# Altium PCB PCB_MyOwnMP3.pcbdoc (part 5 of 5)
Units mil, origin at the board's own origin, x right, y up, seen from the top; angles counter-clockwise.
Board outline 3605 x 4860 mil, 6 copper layers (Top Layer, Inner1, Inner2, Inner3, Inner4, Bottom Layer); 291 components, 261 nets, 1070 pads, 1658 vias.
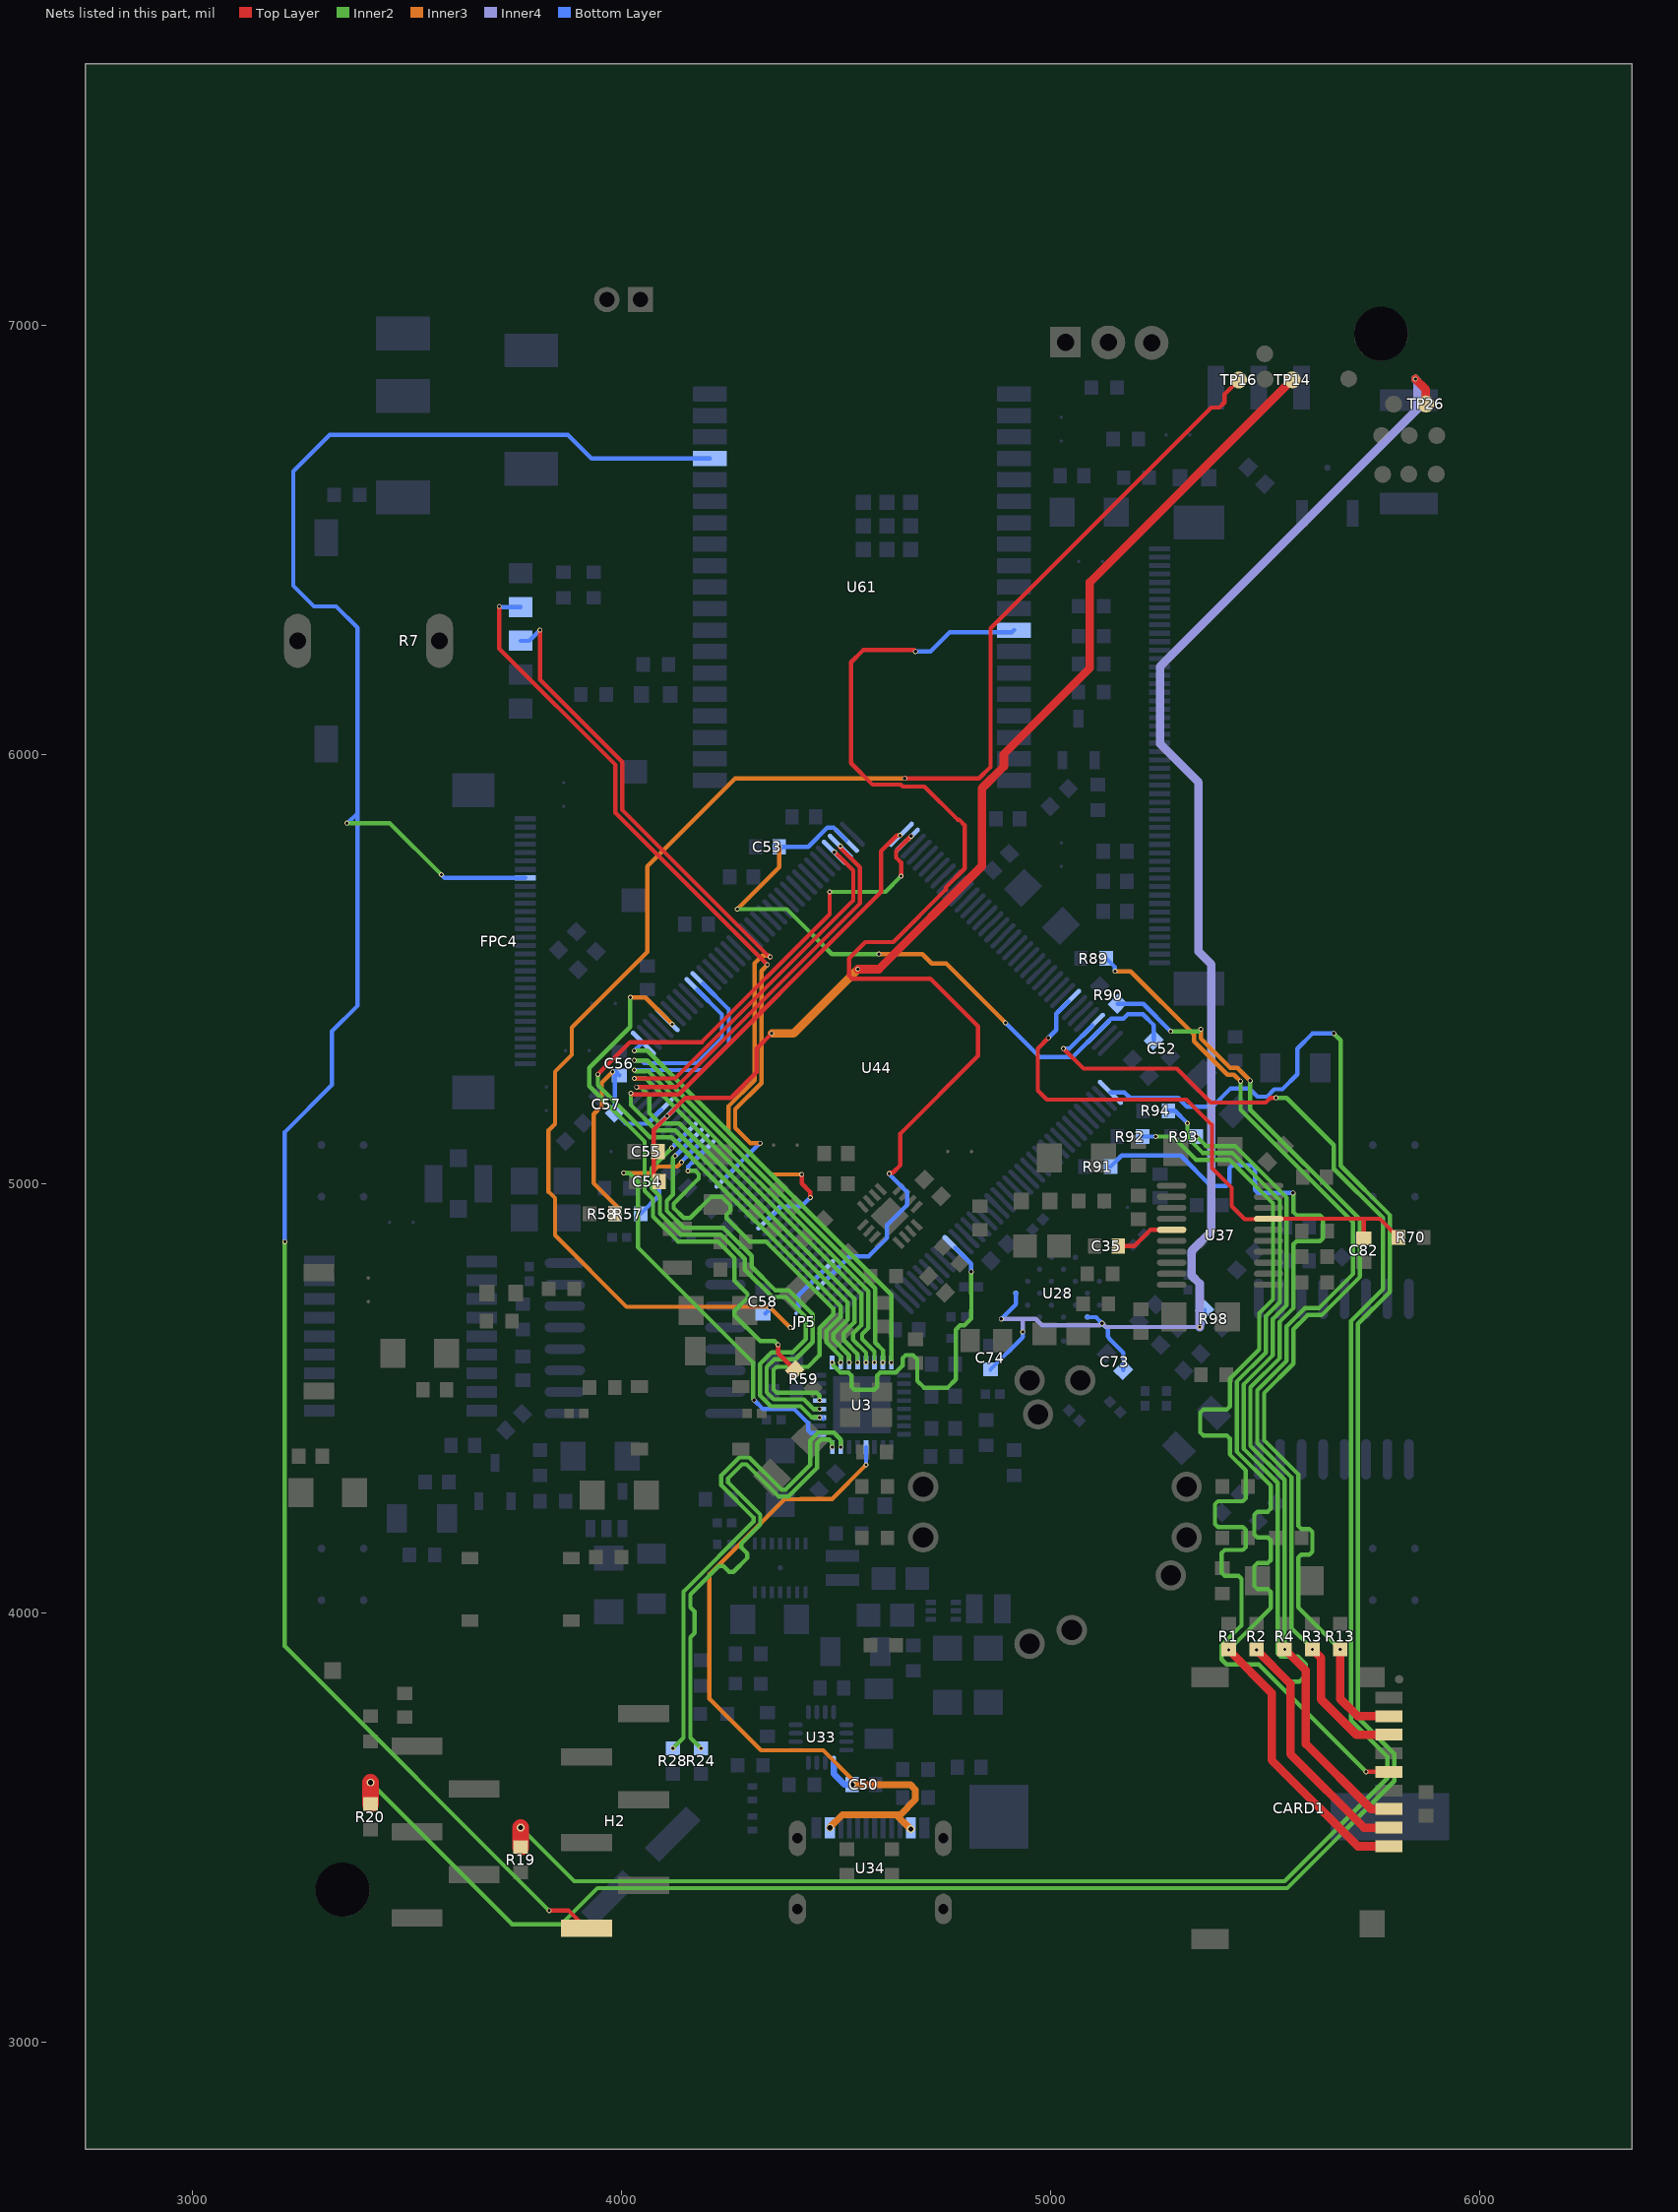
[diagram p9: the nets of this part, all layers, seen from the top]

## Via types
v1: diameter 11.42, hole 7.48, Top Layer to Bottom Layer, 1536 vias
v2: diameter 17.72, hole 11.81, Top Layer to Bottom Layer, 85 vias
v3: diameter 39.37, hole 29.53, Top Layer to Bottom Layer, 11 vias
v4: diameter 11.81, hole 7.87, Top Layer to Bottom Layer, 8 vias
v5: diameter 47.24, hole 23.62, Top Layer to Bottom Layer, 8 vias
v6: diameter 19.68, hole 11.81, Top Layer to Bottom Layer, 4 vias
v7: diameter 24.41, hole 12.2, Top Layer to Bottom Layer, 3 vias
v8: diameter 11.4, hole 7.5, Top Layer to Bottom Layer, 3 vias

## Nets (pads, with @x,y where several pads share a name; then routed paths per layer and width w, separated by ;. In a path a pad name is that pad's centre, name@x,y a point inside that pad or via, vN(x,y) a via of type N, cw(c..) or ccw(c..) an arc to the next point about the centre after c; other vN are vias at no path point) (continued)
SD_A: U44.5 U61.12 | length 2617.7
  Top Layer w10: v1(4623.55,5023.55) 4625.73,5025.73 4632.35,5025.73 4650,5043.38 4650,5117.02 4830.98,5298 4830.98,5366.63 4719.69,5477.93 4537.07,5477.93 4530,5485 4530,5524.79 4568.24,5563.03 4633.58,5563.03 4755.98,5685.44 4755.98,5690.44 4800,5734.45 4800,5835 4786.69,5848.31 4783.09,5848.31 4705.95,5925.45 4655.28,5925.45 4650.72,5930 4585,5930 4535,5980 4535,6215 4563.31,6243.31 4681.69,6243.31 v1(4685,6240)
  Bottom Layer w10: U44.5@4482.25,4781.42 4531.69,4830.86 4575.87,4830.86 4619.02,4874.01 4619.02,4904.02 4665.8,4950.8 4665.8,4980.29 4623.55,5022.54 v1(4623.55,5023.55) ; v1(4685,6240) 4720,6240 4765,6285 4909.33,6285 U61.12@4914.33,6290
SD_CLK: CARD1.5 R92.2 | length 2341
  Top Layer w10: v1(5735,3630) 5788.31,3630 CARD1.5@5788.66,3629.65
  Inner2 w10: v1(5245,5110) 5285,5110 5339.02,5055.98 5416.62,5055.98 5518.27,4954.33 5518.27,4730.67 5486.09,4698.49 5486.09,4613.91 5417.68,4545.5 5417.68,4480.86 5410.61,4473.79 5355.77,4473.79 5348.7,4466.72 5348.7,4420.86 5355.77,4413.79 5410.61,4413.79 5417.68,4406.72 5417.68,4369.5 5455,4332.18 5455,4267.3 5447.93,4260.23 5390.03,4260.23 5382.96,4253.16 5382.96,4207.3 5390.03,4200.23 5447.93,4200.23 5455,4193.16 5455,4153.76 5447.93,4146.69 5405.77,4146.69 5398.7,4139.62 5398.7,4093.76 5405.77,4086.69 5437.93,4086.69 5445,4079.62 5445,3971.11 5398.31,3924.41 5398.31,3891.69 5410,3880 5485,3880 v1(5735,3630)
  Bottom Layer w10: R92.2@5214.66,5110 v1(5245,5110)
SD_CMD: CARD1.3 R4.1 R91.2 | length 2318.2
  Top Layer w19.68: v1(5545.71,3915.34) 5595,3866.05 5595,3695 5746.97,3543.03 CARD1.3@5788.66,3543.03
  Inner2 w10: v1(5545.71,3915.34) 5545,3916.05 5545,4310 5465.64,4389.36 5465.64,4525.64 5534.05,4594.05 5534.05,4678.62 5566.23,4710.81 5566.23,4859.24 5573.3,4866.31 5627.93,4866.31 5635,4873.38 5635,4919.24 5627.93,4926.31 5573.3,4926.31 5566.23,4933.38 5566.23,4975 5565,4976.23 v1(5565,4978.47)
  Bottom Layer w10: R91.2@5139.66,5040 5165.68,5066.02 5303.05,5066.02 5374.07,4995 5409.39,4995 5416.46,5002.07 5416.46,5035.89 5423.53,5042.96 5469.39,5042.96 5476.46,5035.89 5476.46,4985.54 5483.53,4978.47 v1(5565,4978.47)
SD_DATA0: CARD1.7 R3.1 R89.2 | length 2360.8
  Top Layer w19.68: v1(5610,3915.34) 5630,3895.34 5630,3798.7 5712.44,3716.26 CARD1.7@5788.66,3716.26
  Inner2 w10: v1(5442.5,5238.89) 5442.5,5172.5 5705,4910 5705,4790 5625,4710 5592.39,4710 5550.03,4667.63 5550.03,4587.42 5481.62,4519.02 5481.62,4395.98 5560.98,4316.62 5560.98,3965 5610,3915.98 v1(5610,3915.34)
  Inner3 w10: v1(5150,5495) 5186.39,5495 5334.02,5347.38 5334.02,5331.99 5411.99,5254.02 5427.38,5254.02 v1(5442.5,5238.89)
  Bottom Layer w10: R89.2@5129.66,5525 5150,5504.66 v1(5150,5495)
SD_DATA1: CARD1.8 R13.1 R90.2 | length 2310.9
  Top Layer w19.68: v1(5675,3915.34) 5675,3800 5715.43,3759.57 CARD1.8@5788.66,3759.57
  Inner2 w10: v1(5280,5355) 5345,5355 v1(5350,5360) ; v1(5465,5240) 5465,5172.61 5720.98,4916.62 5720.98,4783.38 5631.62,4694.02 5599.02,4694.02 5566.01,4661.01 5566.01,4580.8 5497.61,4512.39 5497.61,4402.61 5576.97,4323.24 5576.97,4202.9 5584.04,4195.83 5602.93,4195.83 5610,4188.76 5610,4142.9 5602.93,4135.83 5584.04,4135.83 5576.97,4128.76 5576.97,4013.37 v1(5675,3915.34)
  Inner3 w10: v1(5350,5360) 5350,5338.61 5418.61,5270 5435,5270 v1(5465,5240)
  Bottom Layer w10: R90.2@5155.97,5419.03 5215.97,5419.03 v1(5280,5355)
SD_DATA2: CARD1.1 R1.1 R94.2 | length 2302.5
  Top Layer w19.68: v1(5415,3913.7) 5515,3813.7 5515,3657.4 5715.98,3456.42 CARD1.1@5788.66,3456.42
  Inner2 w10: v1(5318.71,5140.89) 5318.71,5107.68 5354.42,5071.97 5423.24,5071.97 5534.26,4960.95 5534.26,4724.05 5502.08,4691.87 5502.08,4607.29 5433.67,4538.88 5433.67,4376.12 5513.03,4296.76 5513.03,4243.07 5505.96,4236 5481.87,4236 5474.8,4228.92 5474.8,4183.07 5481.87,4176 5505.96,4176 5513.03,4168.92 5513.03,4123.07 5505.96,4116 5481.87,4116 5474.8,4108.92 5474.8,4063.07 5481.87,4056 5505.96,4056 5513.03,4048.92 5513.03,4011.73 v1(5415,3913.7)
  Bottom Layer w10: R94.2@5274.66,5170 5289.6,5170 v1(5318.71,5140.89)
SD_DATA3: CARD1.2 R2.1 R93.2 | length 2234.9
  Top Layer w19.68: v1(5480,3913.7) 5558.66,3835.04 5558.66,3671.34 5730.27,3499.73 CARD1.2@5788.66,3499.73
  Inner2 w10: v1(5340,5110) 5362.05,5087.95 5429.86,5087.95 5550.24,4967.57 5550.24,4717.43 5518.06,4685.25 5518.06,4600.67 5449.65,4532.26 5449.65,4382.74 5529.02,4303.38 5529.02,3905.98 5536.35,3898.65 5576.35,3898.65 5595,3880 5595,3855 5580,3840 5553.7,3840 v1(5480,3913.7)
SWCLK: R20.1 U44.109 | length 5229.8
  Top Layer w39.37: R20.1@3415,3554.66 v2(3415,3605)
  Inner2 w10: v2(3415,3605) 3745,3275 3860,3275 3944.02,3359.02 5551.62,3359.02 5800.98,3608.38 5800.98,3671.62 5716.09,3756.52 5716.09,4673.48 5790.98,4748.38 5790.98,4926.62 5675.98,5041.62 5675.98,5334.02 v1(5660,5350)
  Bottom Layer w10: U44.109@5139.25,5212.93 5172.07,5212.93 5185.12,5199.88 5297.51,5199.88 5318.38,5179.02 5376.62,5179.02 5419.81,5222.2 5462.8,5222.2 5481.91,5203.09 5504.27,5203.09 5521.18,5220 5540,5220 5575,5255 5575,5315 5610,5350 v1(5660,5350)
SWDIO: R19.1 U44.105 | length 4627.6
  Top Layer w10: v1(5030,5315) 5076.69,5268.31 5294.09,5268.31 5373.38,5189.02 5501.15,5189.02 5512.34,5200.21 v1(5525,5200.21)
  Top Layer w39.37: R19.1@3765,3454.66 v2(3765,3500)
  Inner2 w10: v2(3765,3500) 3890,3375 5545,3375 5785,3615 5785,3665 5700.11,3749.89 5700.11,4680.11 5775,4755 5775,4920 5660,5035 5660,5090 5549.79,5200.21 v1(5525,5200.21)
  Bottom Layer w10: v1(5030,5315) 5043.66,5315 U44.105@5097.49,5368.83
TXD0: FPC4.23 H2.1 U61.35 | length 5407.7
  Top Layer w10: v1(3831.48,3306.48) 3876.98,3306.48 H2.1@3918.46,3265
  Inner2 w10: v1(3215.32,4865) 3215.32,3922.64 v1(3831.48,3306.48) ; v1(3360,5840) 3460,5840 v1(3580,5720)
  Bottom Layer w10: v1(3215.32,4865) 3215.32,5120.32 3325.32,5230.32 3325.32,5355.32 3385,5415 3385,5863.57 ; v1(3360,5840) 3361.43,5840 3385,5863.57 ; v1(3580,5720) 3587.36,5712.64 FPC4.23@3775.53,5712.64 ; U61.35@4205.67,6690 4205.09,6689.42 3930.58,6689.42 3875,6745 3320,6745 3235,6660 3235,6393.38 3283.38,6345 3335,6345 3385,6295 3385,5863.57
ULPI.CLK: R59.1 U44.41 | length 1329.2
  Top Layer w10: v1(4365,4625) 4365,4605 R59.1@4404.03,4565.97
  Inner2 w10: v1(4020.35,5434.26) 4020,5433.91 4020,5365 3925,5270 3925,5227.39 4054.02,5098.38 4054.02,4983.38 4073.47,4963.93 4073.47,4923.72 4131.6,4865.58 4224.42,4865.58 4263.4,4826.6 4263.4,4773.99 4293.68,4743.71 4293.68,4733.71 4263.4,4703.43 4263.4,4693.43 4323.31,4633.53 4356.47,4633.53 v1(4365,4625)
  Inner3 w10: v1(4020.35,5434.26) 4055.74,5434.26 4118.07,5371.93 v1(4118.07,5371.39)
ULPI.D0: U3.24 U44.37 | length 1020
  Inner2 w10: v1(4030,5310) 4060,5310 4628.84,4741.16 v1(4628.84,4583.42)
  Bottom Layer w10: v1(4030,5310) 4047.07,5327.07 U44.37@4050.75,5327.07
ULPI.D1: U3.23 U44.46 | length 1329.5
  Inner2 w10: v1(4030,5287.4) 4059.99,5287.4 4590.98,4756.41 4590.98,4630.33 4609.15,4612.17 v1(4609.15,4583.42)
  Bottom Layer w10: v1(4030,5287.4) 4046.21,5287.4 4052.67,5280.94 4175.94,5280.94 4234.02,5339.02 4234.02,5394.36 U44.46@4176.03,5452.35
ULPI.D2: U3.22 U44.47 | length 1354.2
  Inner2 w10: v1(4030.05,5264.95) 4032.99,5262.01 4056.91,5262.01 4057.62,5262.71 4062.08,5262.71 4575,4749.79 4575,4664 4560.59,4649.59 4560.59,4638.12 4589.47,4609.24 v1(4589.47,4583.42)
  Bottom Layer w10: v1(4030.05,5264.95) 4189.95,5264.95 4250,5325 4250,5406.2 U44.47@4189.94,5466.26
ULPI.D3: U3.21 U44.69 | length 1730.4
  Top Layer w10: v1(4030,5245.31) 4125.1,5245.31 4540,5660.21 4540,5730 4497.51,5772.49 v1(4496.17,5772.49)
  Inner2 w10: v1(4030,5245.31) 4056.87,5245.31 4558.68,4743.5 4558.68,4670.29 4539.2,4650.8 4539.2,4636.91 4569.78,4606.33 v1(4569.78,4583.42)
ULPI.D4: U3.20 U44.70 | length 1758
  Top Layer w10: v1(4035,5225) 4127.39,5225 4555.98,5653.59 4555.98,5736.62 4510.09,5782.51 v1(4510.09,5786.41)
  Inner2 w10: v1(4035,5225) 4045,5225 4065,5205 4065,5165 4089.64,5140.36 4134.64,5140.36 4542.7,4732.3 4542.7,4676.91 4517.9,4652.1 4517.9,4635.61 4550.1,4603.4 v1(4550.1,4583.42)
ULPI.D5: U3.19 U44.73 | length 1826
  Top Layer w10: v1(4021.69,5210.76) 4024.14,5208.31 4133.31,5208.31 4605,5680 4605,5775 4641.47,5811.47 v1(4649.28,5811.47)
  Inner2 w10: v1(4021.69,5210.76) 4021.69,5183.31 4080.62,5124.38 4125.62,5124.38 4526.71,4723.29 4526.71,4683.53 4493.51,4650.32 4493.51,4637.39 4530.41,4600.49 v1(4530.41,4583.42)
ULPI.D6: U3.18 U44.74 | length 2003.8
  Top Layer w10: v1(3945,5255) 4020,5330 4187.18,5330 4485,5627.82 v1(4485,5680) ; v1(4651.54,5716.46) 4651.54,5748.46 4640,5760 4640,5775 v1(4675,5810)
  Inner2 w10: v1(3945,5255) 3945,5230 4066.61,5108.39 4116.61,5108.39 4510.73,4714.27 4510.73,4690.15 4477.52,4656.94 4477.52,4630.77 4510.73,4597.56 v1(4510.73,4583.42) ; v1(4485,5680) 4615.08,5680 v1(4651.54,5716.46)
ULPI.D7: U3.17 U44.135 | length 802.8
  Inner2 w10: v1(4491.04,4583.42) 4494.04,4580.42 4494.04,4575.96 4510,4560 4528.73,4560 4535.8,4552.93 4535.8,4527.19 4542.87,4520.12 4588.73,4520.12 4595.8,4527.19 4595.8,4552.93 4602.87,4560 4639.03,4560 4655.53,4576.51 4655.53,4593.8 4662.6,4600.87 4679.13,4600.87 4689.13,4590.87 4689.13,4540.87 4705,4525 4760,4525 4779.02,4544.02 4779.02,4660.13 4789.02,4670.13 4799.24,4670.13 4814.97,4685.86 4814.97,4705.31 4815.22,4705.56 4815.22,4743.97 4814.97,4744.22 v1(4815,4795)
  Bottom Layer w10: U44.135@4777.35,4851.02 4815,4813.37 v1(4815,4795)
ULPI.DIR: U3.12 U44.28 | length 1037.3
  Inner2 w10: v8(4125,5065) 4120,5060 4120,4974.77 4105.43,4960.21 4105.43,4936.96 4144.85,4897.55 4237.66,4897.55 4303.35,4831.86 4303.35,4806.65 4357.97,4752.03 4389.42,4752.03 4445.55,4695.89 4445.55,4631.24 4405.49,4591.18 4356.54,4591.18 4338.43,4573.06 4338.43,4513.96 4354.86,4497.53 4425,4497.53 4447.29,4475.24 v1(4461.58,4475.24)
  Bottom Layer w10: v8(4125,5065) 4125.53,5065 U44.28@4162.1,5101.57
ULPI.NXT: U3.11 U44.29 | length 1105.8
  Inner2 w10: v8(4116.8,5083.2) 4101.89,5068.3 4101.89,5068 4092,5058.11 4091.7,5058.11 4070,5036.4 4070,4990 4089.45,4970.55 4089.45,4930.34 4138.22,4881.57 4231.04,4881.57 4287.37,4825.24 4287.37,4800.03 4351.35,4736.04 4382.8,4736.04 4429.57,4689.27 4429.57,4637.86 4398.87,4607.16 4349.92,4607.16 4322.44,4579.68 4322.44,4507.34 4348.24,4481.54 4417.46,4481.54 4443.53,4455.47 v1(4461.58,4455.47)
  Bottom Layer w10: v8(4116.8,5083.2) 4148.19,5114.59 U44.29@4148.19,5115.49 ; U3.11@4461.58,4455.55 4466.82,4455.55 U3.11@4470,4452.37
ULPI.RST: U3.9 U44.27 | length 1056.1
  Inner2 w10: v1(4005,5024.93) 4018.1,5024.93 4038.03,5005 4038.03,4851.97 4306.46,4583.54 4306.46,4498.54 v1(4309.03,4495.97)
  Inner3 w10: v1(4005,5024.93) 4069.93,5024.93 4085,5040 4130,5040 v1(4140,5050)
  Bottom Layer w10: v1(4140,5050) 4140,5051.62 U44.27@4176.03,5087.65 ; v1(4309.03,4495.97) 4330,4475 4402.76,4475 4434.85,4442.91 4434.85,4425.81 4441.28,4419.37 4458.39,4419.37 U3.9@4461.58,4416.18
ULPI.STP: U3.13 U44.26 | length 1143.6
  Inner2 w10: v8(4155,5030) 4172.39,5030 4180.11,5022.28 4180.11,5012.28 4121.42,4953.58 4121.42,4943.58 4145,4920 4160,4920 4209.85,4969.85 4232.54,4969.85 4254.32,4948.08 4254.32,4938.08 4245.14,4928.91 4245.14,4918.91 4299.05,4865 4337.39,4865 4493.27,4709.12 4493.27,4695.3 4461.54,4663.56 4461.54,4600.61 4434.44,4573.51 4361.48,4573.51 4354.41,4566.44 4354.41,4520.58 4361.48,4513.51 4454.51,4513.51 4461.58,4506.44 v1(4461.58,4495.19)
  Bottom Layer w10: v8(4155,5030) 4155,5040 4188.73,5073.73 U44.26@4189.94,5073.73
USB_5V: C50.2 U3.4 U33.13 U34.A4B9 U34.B4A9 | length 1755.4
  Inner3 w10: v2(4537.44,3600) 4537.44,3612.56 4470,3680 4325,3680 4205,3800 4205,4090 4380,4265 4416.63,4265 4417.3,4265.67 4490.67,4265.67 v1(4570,4345)
  Inner3 w16: v2(4485.51,3499.49) 4485.51,3500.51 4515,3530 4640,3530 ; v2(4537.44,3600) 4673.69,3600 4685,3588.69 4685,3565 4650,3530 4640,3530 ; v2(4674.48,3496.34) 4673.66,3496.34 4640,3530
  Bottom Layer w10: U3.4@4569.9,4386.58 4570,4386.48 v1(4570,4345)
  Bottom Layer w15: U33.13@4494.54,3650.94 4494.54,3625.46 4520,3600 v2(4537.44,3600)
USB_DM: R24.1 U3.8 | length 1185.1
  Inner2 w10: v1(4185,3684.66) 4160.5,3709.16 4160.5,3943.26 4170.5,3953.26 4170.5,4003.26 4160.5,4013.26 4160.5,4042.87 4227.19,4109.56 4237.19,4109.56 4250.88,4095.88 4260.88,4095.88 4293.3,4128.3 4293.3,4138.3 4279.62,4151.99 4279.62,4161.99 4323.48,4205.85 4323.48,4229.11 4248.59,4303.99 4248.59,4313.99 4281.02,4346.42 4291.02,4346.42 4365.9,4271.53 4389.16,4271.53 4456,4338.37 4456,4395 4465,4404 4484.09,4404 4491.16,4396.93 v1(4491.16,4386.58)
USB_DP: R28.2 U3.7 | length 1183.4
  Inner2 w10: v1(4120,3684.66) 4144.5,3709.16 4144.5,4049.5 4307.48,4212.48 4307.48,4222.48 4232.59,4297.36 4232.59,4320.62 4274.39,4362.42 4297.65,4362.42 4372.53,4287.53 4382.53,4287.53 4440,4345 4440,4401.63 4458.37,4420 4495,4420 4510.84,4404.16 v1(4510.84,4386.58)
V_OUTL: R7.4 U44.15 | length 1894.9
  Top Layer w10: v1(3810,6290) 3810,6174.35 4001.97,5982.38 4001.97,5870.64 4344.26,5528.35 v1(4346.65,5528.35) ; v1(4420,5021.69) 4420,5000.59 4439.82,4980.77 v1(4439.82,4967.61)
  Inner3 w10: v1(4346.65,5528.35) 4343.31,5531.69 4328.09,5531.69 4310,5513.61 4310,5241.21 4249.02,5180.23 4249.02,5120.98 4348.31,5021.69 v1(4420,5021.69)
  Bottom Layer w10: R7.4@3764.84,6265 3785,6265 v1(3810,6290) ; U44.15@4343.06,4920.62 4347.56,4920.62 4374.08,4947.14 4419.35,4947.14 v1(4439.82,4967.61)
V_OUTR: R7.2 U44.22 | length 1737.2
  Top Layer w10: v1(3715,6345) 3715,6246.75 3985.98,5975.76 3985.98,5864.02 v1(4340,5510)
  Inner3 w10: v1(4323.08,5094.47) 4300.53,5094.47 4265,5130 4265,5173.61 4325.98,5234.59 4325.98,5495.98 v1(4340,5510)
  Bottom Layer w10: v1(3715,6345) 3716.26,6343.74 R7.2@3764.84,6343.74 ; U44.22@4245.62,5018.06 4322.03,5094.47 v1(4323.08,5094.47)
VBAT: C58.2 JP5.1 TP16.1 U44.6 | length 3780
  Top Layer w10: v1(4660,5944.33) 4833.34,5944.33 4860,5970.99 4860,6294.15 5374.29,6808.44 5393.33,6808.44 5405.53,6820.64 5405.53,6839.68 TP16.1@5438.58,6872.74
  Inner3 w10: v1(4393.15,4664.58) 4347.02,4710.7 v1(4345.7,4710.7) 4343.09,4713.31 4011.69,4713.31 3845,4880 3845,4966.4 3830,4981.4 3830,5124.21 3845,5139.21 3845,5261.19 3884.17,5300.37 3884.17,5364.17 4060,5540 4060,5739.33 4265,5944.33 v1(4660,5944.33)
  Bottom Layer w10: C58.2@4335,4697.44 4345.7,4708.14 v1(4345.7,4710.7) ; 4411.9,4703.09 4411.9,4738.92 U44.6@4468.33,4795.35
VCAP: C52.2 C53.2 U44.71 U44.106 | length 1573.2
  Inner2 w10: v1(4270,5640) 4385,5640 4490,5535 v1(4600,5535)
  Inner3 w10: v1(4270,5640) 4367.6,5737.6 v1(4367.6,5785) ; v1(4600,5535) 4701.39,5535 4723.09,5513.31 4756.69,5513.31 v1(4895,5375)
  Bottom Layer w10: v1(4367.6,5785) 4435,5785 4480,5830 4494.3,5830 U44.71@4524.01,5800.33 ; v1(4895,5375) 4975,5295 5051.5,5295 U44.106@5111.41,5354.91 5141.29,5384.79 5169.79,5384.79 5180,5395 5215,5395 5240.51,5369.49 C52.2@5240.51,5334.49
VDDA: C56.1 C57.2 R57.1 R58.1 U44.33 | length 622
  Inner3 w10: v1(3979.3,5260.7) 3954.02,5235.41 3954.02,5181.23 3935,5162.22 3935,5001.34 3995.35,4940.99 v4(3995.35,4930)
  Bottom Layer w10: C56.1@3995,5252.44 3986.74,5260.7 v1(3979.3,5260.7) 3984.5,5255.5 C57.2@3984.49,5165.51 4010,5140 4060,5140 4091.17,5171.17 U44.33@4092.51,5171.17
VNEG: C35.1 U37.5 | length 140.1
  Top Layer w10: C35.1@5157.56,4855 5195,4855 5232.79,4892.79 U37.5@5281.97,4892.79
VREF+: C54.2 C55.1 R57.2 TP14.1 U44.32 | length 2703.1
  Top Layer w10: v4(4087.56,5005) 4074.85,5017.7 v4(4074.85,5065.15) 4074.85,5125.67 v4(4106.43,5157.25) 4149.18,5200 4255,5200 4315,5260 4315,5315 v1(4350,5350)
  Top Layer w19.68: v1(4550.83,5500) 4600,5500 4840,5740 4840,5921.54 4890.96,5972.5 4890.96,6000.96 5091.54,6201.54 5091.54,6401.32 TP14.1@5563.23,6873.01
  Inner3 w19.68: v1(4350,5350) 4400.83,5350 v1(4550.83,5500)
  Bottom Layer w10: R57.2@4044.66,4930 4087.56,4972.9 v4(4087.56,5005)
VSSQ: C73.2 C74.2 R98.1 TP26.1 U28.C1 U28.E5 | length 3516.7
  Top Layer w19.68: v1(5850,6875) 5874.84,6850.16 TP26.1@5874.84,6816.87
  Inner4 w10: v1(4885,4685) 4934.56,4685 ; v1(4935,4655) 4935,4684.56 4934.56,4685 ; v1(5347.35,4666.23) 5128.77,4666.23 v1(5120,4675) 5115,4670 4980,4670 4965,4685 4934.56,4685
  Inner4 w19.68: v1(5347.35,4666.23) 5347.35,4767.19 5328.46,4786.08 5328.46,4843.55 5374.69,4889.78 5374.69,5510.77 5345,5540.46 5345,5935 5255,6025 5255,6205 5855,6805 5855,6870 v1(5850,6875)
  Bottom Layer w10: C74.2@4860,4567.44 4935,4642.44 v1(4935,4655) ; v1(4885,4685) 4919.26,4719.26 4919.26,4744.39 U28.E5@4918.65,4745 ; U28.C1@5085.68,4689.32 5105.68,4689.32 v1(5120,4675) 5133.2,4661.8 5133.2,4644.19 5136.45,4640.94 5136.45,4639.14 5169.49,4606.1 C73.2@5169.49,4565.51 ; v1(5347.35,4666.23) 5359.03,4677.9 R98.1@5359.03,4705.97
XSMT: C82.1 R70.1 U37.17 U44.101 | length 1349.2
  Top Layer w10: v1(4995,5340) 4970,5315 4970,5217.29 4991.3,5195.98 5316.62,5195.98 5375.98,5136.62 5375.98,5036.62 5421.97,4990.64 5421.97,4948.03 5452.5,4917.5 5507.14,4917.5 U37.17@5508.03,4918.39 5730,4918.39 ; C82.1@5730,4872.56 5730,4918.39 ; R70.1@5810.35,4875 5766.96,4918.39 5730,4918.39
  Bottom Layer w10: v1(4995,5340) 5013.23,5358.23 5013.23,5395.93 U44.101@5041.81,5424.51
pads on no net: CN1.2 FPC1.11 FPC1.12 FPC1.13 FPC1.14 FPC1.15 FPC1.16 FPC1.33 FPC1.34 FPC1.44 FPC1.45 FPC1.46 FPC1.47 FPC4.13 L2.2 U3.3 U3.5 U3.10 U5.4 U5.5 U5.6 U5.11 U5.12 U5.13 U5.14 U12.5 U12.13 U12.15 U12.16 U12.17 U12.18 U16.4 U27.4 U28.A2 U28.A5 U28.B5 U28.C2 U28.C5 U34.A8 U34.B8 U44.7 U44.44 U44.103 U44.110 U44.128 U44.136 U44.140 U61.4 U61.5 U61.6 U61.7 U61.14 U61.17 U61.18 U61.19 U61.20 U61.21 U61.22 U61.27 U61.28 U61.29 U61.32 U67.14

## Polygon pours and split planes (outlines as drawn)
GND on Top Layer (solid, remove dead copper, pour order 0): 3035,7315 6070,7315 6070,3010 3035,3010
GND on Bottom Layer (solid, remove dead copper, pour order 2): 3015,7325 6070,7325 6070,3010 3015,3010
GND on Inner1 (solid, remove dead copper): 3000,7350 6070,7350 6070,3000 3000,3000
GND on Inner4 (solid, remove dead copper): 3000,7360 6105,7360 6105,3000 3000,3000

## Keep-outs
Board Outline Layer:
  lines w10: 3420,7135 4165,7135 4190,7110 4190,6925 4250,6865 4870,6865 4930,6925 4930,7110 4955,7135 5705,7135 ; 3421.22,7134.99 ccw(c3421.22,6898.77) 3185,6898.77 3185,3434.21 ccw(c3421.22,3434.21) 3421.22,3197.99 5704.68,3197.99 ccw(c5704.68,3434.21) 5940.9,3434.21 5940.9,6898.77 ccw(c5704.68,6898.77) 5704.68,7134.99

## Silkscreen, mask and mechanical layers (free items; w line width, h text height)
Top Silkscreen Layer:
  drawing of 276 lines, arcs and shapes, not listed
  text "U" at 5385,6880 h39.37
  text "P" at 5825,6790 h39.37
  text "Y" at 5540,6730 h118.11 r315
  text "MORPH" at 5585,6695 h118.11 r270
  text "SLEEP" at 5080,6690 h118.11
  text "D" at 5825,6680 h39.37
  text "SAIL" at 4605,5560 h314.96
  text "THE PROTOTYPE" at 4695,5510 h98.43
  text "v1.0" at 5551.24,5140.39 h59.06
  text "built by: / sleepymorph" at 4345,3650 h78.74
Bottom Silkscreen Layer:
  drawing of 6 lines, arcs and shapes, not listed
  text "funded by:" at 3910,3905 h90.55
